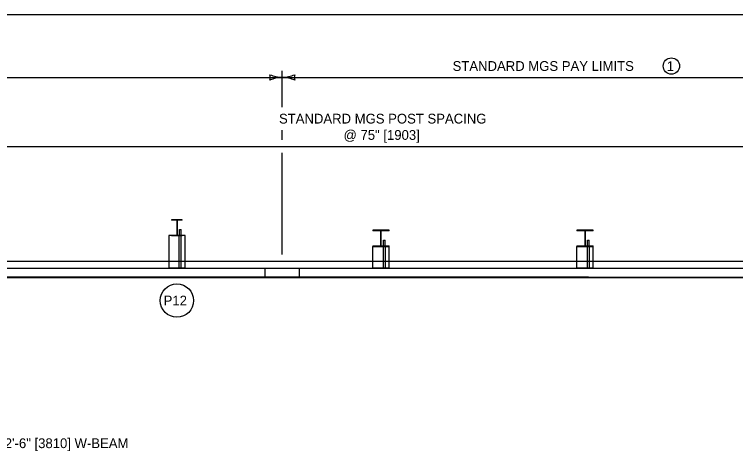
# Model space of a CAD drawing. Extents: x 49991 to 50160, y 49948 to 50051.
# Drawn here: x 50006.556 to 50010.973, y 49996.312 to 49998.999 of the extents above; entities that cross this region are included whole.
import ezdxf

# ---------------------------------------------------------------- set-up
doc = ezdxf.new("R2010")
doc.units = 0
for name, color, linetype in [('Level 1', 7, 'Continuous'), ('Level 2', 7, 'Continuous'), ('Level 3', 7, 'Continuous'), ('Level 4', 7, 'Continuous')]:
    doc.layers.add(name, color=color, linetype=linetype)

msp = doc.modelspace()

# ---------------------------------------------------------------- linework, layer by layer
at = {"layer": 'Level 1'}
for p, q in [((50007.5841, 49997.7401), (50007.5185, 49997.7401)), ((50007.5185, 49997.7401), (50007.5185, 49997.7369)), ((50007.5841, 49997.7369), (50007.5185, 49997.7369)), ((50007.5499, 49997.7369), (50007.5499, 49997.6462)), ((50007.5527, 49997.7369), (50007.5527, 49997.6462)), ((50007.5841, 49997.7369), (50007.5841, 49997.7401)), ((50007.5664, 49997.6795), (50007.5769, 49997.6795)), ((50007.5664, 49997.6462), (50007.5664, 49997.6795)), ((50007.5769, 49997.6462), (50007.5769, 49997.6795)), ((50008.8508, 49997.6764), (50008.7508, 49997.6764)), ((50008.7508, 49997.6764), (50008.7508, 49997.672)), ((50008.8508, 49997.672), (50008.7508, 49997.672)), ((50008.7989, 49997.672), (50008.7989, 49997.5807)), ((50008.8027, 49997.5807), (50008.8027, 49997.672)), ((50008.8508, 49997.672), (50008.8508, 49997.6764)), ((50010.1008, 49997.6763), (50010.0008, 49997.6763)), ((50010.0008, 49997.6763), (50010.0008, 49997.672)), ((50010.1008, 49997.672), (50010.0008, 49997.672)), ((50010.0489, 49997.672), (50010.0489, 49997.5807)), ((50010.0527, 49997.5807), (50010.0527, 49997.672)), ((50010.1008, 49997.672), (50010.1008, 49997.6763)), ((50007.5008, 49997.6429), (50007.5008, 49997.4429)), ((50007.6008, 49997.6429), (50007.5008, 49997.6429)), ((50007.5185, 49997.6429), (50007.5185, 49997.6462)), ((50007.5185, 49997.6462), (50007.5841, 49997.6462)), ((50007.5185, 49997.6429), (50007.5841, 49997.6429)), ((50007.5841, 49997.6462), (50007.5841, 49997.6429)), ((50007.6008, 49997.4429), (50007.6008, 49997.6429)), ((50008.8164, 49997.614), (50008.8269, 49997.614)), ((50008.8164, 49997.5807), (50008.8164, 49997.614)), ((50008.8269, 49997.5807), (50008.8269, 49997.614)), ((50010.0664, 49997.614), (50010.0769, 49997.614)), ((50010.0664, 49997.5807), (50010.0664, 49997.614)), ((50010.0769, 49997.5807), (50010.0769, 49997.614)), ((50008.7508, 49997.5807), (50008.7508, 49997.5764)), ((50008.7508, 49997.5807), (50008.8508, 49997.5807)), ((50008.7508, 49997.5764), (50008.8508, 49997.5764)), ((50008.7508, 49997.443), (50008.7508, 49997.5764)), ((50008.8508, 49997.5764), (50008.7508, 49997.5764)), ((50008.8508, 49997.5764), (50008.8508, 49997.5807)), ((50008.8508, 49997.443), (50008.8508, 49997.5764)), ((50010.0008, 49997.5807), (50010.0008, 49997.5763)), ((50010.0008, 49997.5807), (50010.1008, 49997.5807)), ((50010.0008, 49997.5763), (50010.1008, 49997.5763)), ((50010.0008, 49997.443), (50010.0008, 49997.5763)), ((50010.1008, 49997.5763), (50010.0008, 49997.5763)), ((50010.1008, 49997.5763), (50010.1008, 49997.5807)), ((50010.1008, 49997.443), (50010.1008, 49997.5763)), ((50006.3508, 49997.4869), (50007.5008, 49997.4869)), ((50007.6008, 49997.4869), (50008.7508, 49997.4868)), ((50008.8508, 49997.4868), (50010.0008, 49997.4868)), ((50010.1008, 49997.4868), (50011.2508, 49997.4868)), ((49999.8238, 49997.4433), (50011.6716, 49997.4428)), ((50007.6008, 49997.4429), (50007.5008, 49997.4429)), ((50008.0917, 49997.3868), (50008.0917, 49997.4429)), ((50008.8508, 49997.443), (50008.7508, 49997.443)), ((50010.1008, 49997.443), (50010.0008, 49997.443)), ((49999.8238, 49997.387), (50011.6716, 49997.3866))]:
    msp.add_line(p, q, dxfattribs=at)
msp.add_lwpolyline([(49999.3835, 49998.9992), (50016.7501, 49998.9992), (50016.7501, 49987.7988), (49999.3835, 49987.7988)], close=True, dxfattribs=at)
at = {"layer": 'Level 2'}
for centre, radius in [((50010.5794, 49998.6827), 0.05), ((50007.5509, 49997.2442), 0.1026)]:
    msp.add_circle(centre, radius, dxfattribs=at)
at = {"layer": 'Level 3'}
for p, q in [((50008.1966, 49998.4299), (50008.1966, 49998.6527)), ((50000.6957, 49998.6127), (50008.1966, 49998.6127)), ((50008.1966, 49998.6127), (50011.5324, 49998.6127)), ((50008.1966, 49998.2299), (50008.1966, 49998.2899)), ((50006.3216, 49998.1899), (50011.5324, 49998.1899)), ((50008.1966, 49997.5268), (50008.1966, 49998.1499)), ((50007.5716, 49997.3868), (50006.3216, 49997.3868)), ((50008.8216, 49997.3868), (50007.5716, 49997.3868)), ((50010.0716, 49997.3868), (50008.8216, 49997.3868)), ((50010.0716, 49997.3868), (50011.3216, 49997.3868)), ((50010.0716, 49997.3868), (50010.6966, 49997.3868))]:
    msp.add_line(p, q, dxfattribs=at)
for centre, radius, start, end in [((50008.2058, 49998.8348), 0.2223, 247.456, 267.6395), ((50008.0684, 49998.6127), 0.0548, 342.1388, 17.8612), ((50008.1852, 49998.8454), 0.233, 272.8273, 292.0772), ((50008.3249, 49998.6127), 0.0548, 162.1388, 197.8612), ((50008.2081, 49998.38), 0.233, 92.8273, 112.0772), ((50008.1875, 49998.3905), 0.2223, 67.456, 87.6395)]:
    msp.add_arc(centre, radius, start, end, dxfattribs=at)
at = {"layer": 'Level 4'}
for p, q in [((50007.5654, 49997.4429), (50007.5654, 49997.6429)), ((50007.5779, 49997.4429), (50007.5779, 49997.6429)), ((50008.8154, 49997.443), (50008.8154, 49997.5764)), ((50008.8154, 49997.443), (50008.8154, 49997.5764)), ((50008.8279, 49997.443), (50008.8279, 49997.5764)), ((50008.8279, 49997.443), (50008.8279, 49997.5764)), ((50010.0654, 49997.443), (50010.0654, 49997.5763)), ((50010.0654, 49997.443), (50010.0654, 49997.5763)), ((50010.0779, 49997.443), (50010.0779, 49997.5763)), ((50010.0779, 49997.443), (50010.0779, 49997.5763)), ((50007.5008, 49997.4869), (50007.6008, 49997.4869)), ((50008.7508, 49997.4868), (50008.8508, 49997.4868)), ((50010.0008, 49997.4868), (50010.1008, 49997.4868)), ((50008.3016, 49997.3868), (50008.3016, 49997.4429))]:
    msp.add_line(p, q, dxfattribs=at)

# ---------------------------------------------------------------- texts
at = {"layer": 'Level 2'}
for s, p in [('STANDARD MGS PAY LIMITS', (50009.2397, 49998.6527)), ('1', (50010.5513, 49998.6518)), ('STANDARD MGS POST SPACING', (50008.1763, 49998.3299)), ('@ 75" [1903]', (50008.5718, 49998.2299)), ('P12', (50007.4697, 49997.2144)), ('12\'-6" [3810] W-BEAM', (50006.4522, 49996.3394))]:
    msp.add_text(s, height=0.06, dxfattribs=at).set_placement(p)

doc.saveas('drawing.dxf')
